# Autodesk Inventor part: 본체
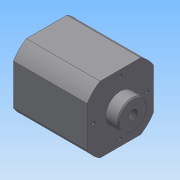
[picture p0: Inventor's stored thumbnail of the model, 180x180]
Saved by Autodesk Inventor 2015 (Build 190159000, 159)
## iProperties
Created: 2020-02
Part Number: 본체
Material: 일반
Document SubType Name: Modeling
Designer: user
Density: 1 g/cm^3
Appearance: 기본값
Author: user
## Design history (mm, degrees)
sketch "스케치1"
  geometry: L1 (-19.551, -32)-(19.551, -32); L2 (32, -19.551)-(32, 19.551); L3 (19.551, 32)-(-19.551, 32); L4 (-32, 19.551)-(-32, -19.551); L5 (-32.2, -33.191)-(30.823, 31.771); L6 (30.823, -32.229)-(-25.919, 27.101); A1 r 37.5 centre (0, 0) between (-19.551, 32) and (-32, 19.551); A2 r 37.5 centre (0, 0) between (-32, -19.551) and (-19.551, -32); A3 r 37.5 centre (0, 0) between (19.551, -32) and (32, -19.551); A4 r 37.5 centre (0, 0) between (32, 19.551) and (19.551, 32); 1 further point
  constraints: 12 end point, 9 point on circle, 4 centre point, 2 parallel, 2 point on line, 1 coincident, 1 horizontal, 1 perpendicular
  dimensions: "d1" = 64 distance of L6.start L5.end
extrude "돌출1" new body sketch "스케치1" distance "d3" = 71; taper "d4" = 0 deg
sketch "스케치2"
  geometry: C1 r 14 at (0, 0); A1 r 37.5 centre (0, 0) between (-32, -19.551) and (-19.551, -32) reference
  constraints: 1 centre point, 1 coincident
  dimensions: "d6" = 28 diameter of C1
extrude "돌출2" join sketch "스케치2" distance "d7" = 12; taper "d8" = 0 deg
chamfer "모따기1" distance "d9" = 1; stored, may be unused: second distance "d10" = 2, angle "d11" = 45 deg
hole "구멍1" diameter "d14" = 8.917; stored, may be unused: countersink angle "d18" = 15 deg, drill point angle "d20" = 118 deg; dims "d12" = 10, "d13" = 10, "d15" = 14, "d16" = 40, "d17" = 2, "d19" = 17
hole "구멍3" diameter "d32" = 40; stored, may be unused: countersink angle "d36" = 15 deg, drill point angle "d38" = 0 deg; dims "d33" = 14, "d34" = 40, "d35" = 2, "d37" = 62, "d84" = 10, "d85" = 10
chamfer "모따기2" distance "d39" = 1.8; stored, may be unused: second distance "d40" = 2, angle "d41" = 15 deg
sketch "스케치3" dims "d42" = 52
  geometry: L1 (0, 0)-(0, 34.877); C1 r 2.623 at (0, 26); A1 r 37.5 centre (0, 0) between (-32, -19.551) and (-19.551, -32) reference
  constraints: 2 end point, 1 centre point, 1 coincident, 1 point on line, 1 vertical, 1 vertical alignment, 2 other
hole "구멍4" sketch "스케치3" at (0, 26) diameter "d43" = 3.242; stored, may be unused: countersink angle "d47" = 15 deg, drill point angle "d49" = 118 deg; dims "d44" = 10, "d45" = 40, "d46" = 2, "d48" = 12
sketch "스케치4" dims "d53" = 52
  geometry: L1 (0, 0)-(0, -38.592); C1 r 20.482 at (0, 0) reference; C2 r 2.624 at (0, -26)
  constraints: 2 end point, 1 centre point, 1 coincident, 1 point on line, 1 vertical, 1 vertical alignment, 2 other
hole "구멍5" sketch "스케치4" at (0, -26) diameter "d54" = 3.242; stored, may be unused: countersink angle "d58" = 15 deg, drill point angle "d60" = 118 deg; dims "d55" = 10, "d56" = 40, "d57" = 2, "d59" = 12
sketch "스케치5"
  geometry: L1 (0, 39.102)-(0, 0) reference; L2 (0, 0)-(71, 0) reference; L3 (71, 39.102)-(71, 0) reference; L4 (0, 39.102)-(71, 39.102) reference; L5 (17, 17)-(17, 22.102); L6 (17, 22.102)-(54, 22.102); L7 (54, 22.102)-(54, 17); L8 (54, 17)-(17, 17); L9 (0, 19.551)-(32.17, 19.551); C1 r 1.388 at (17, 19.551)
  constraints: 10 end point, 1 centre point, 1 horizontal, 1 midpoint, 1 point on line, 3 other
  dimensions: "d64" = 17 distance between parallel lines of L1 L5
hole "구멍6" sketch "스케치5" at (17, 19.551) diameter "d65" = 8.917; stored, may be unused: countersink angle "d69" = 15 deg, drill point angle "d71" = 118 deg; dims "d66" = 6, "d67" = 40, "d68" = 2, "d70" = 9
hole "구멍7" diameter "d74" = 4; stored, may be unused: countersink angle "d78" = 15 deg, drill point angle "d80" = 0 deg; dims "d72" = 10, "d73" = 10, "d75" = 6, "d76" = 40, "d77" = 2, "d79" = 30
sketch "스케치6"
  geometry: L1 (71, 39.102)-(71, 0) reference; L2 (71, -12.449)-(71, 0) reference; L3 (71, 19.551)-(0, 19.551); L4 (51, 19.551)-(51, -15.129); 1 further point
  constraints: 4 end point, 1 coincident, 1 horizontal, 1 midpoint, 1 point on line, 1 vertical, 1 other
feature "엠보싱1" sketch "스케치6" dims "d1" = 64, "d17" = 2, "d82" = 0.5, "d83" = 0
hole "구멍8" diameter "d88" = 4; stored, may be unused: countersink angle "d92" = 90 deg, drill point angle "d94" = 0 deg; dims "d86" = 10, "d87" = 10, "d89" = 6, "d90" = 4, "d91" = 2, "d93" = 100
node "솔리드1"
pattern_circular "원형 패턴1" dims angle "d51" = 360 deg
pattern_circular "원형 패턴2" dims angle "d62" = 360 deg
other parameters: "d2" = 75
